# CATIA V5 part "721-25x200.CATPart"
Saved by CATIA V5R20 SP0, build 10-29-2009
Part number: 721-25x200
Definition: NONE
Nomenclature: 721-25x200
Source: Unknown
Description: 721-25x200
Bounding box of the stored display mesh (mm): x -90 to 110, y -24 to 24, z -24 to 24
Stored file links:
  C:\Users\Utente\Desktop\IO LAVORO\3D X SITO CF\X SITO\721\721-25x200.CATPart
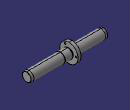
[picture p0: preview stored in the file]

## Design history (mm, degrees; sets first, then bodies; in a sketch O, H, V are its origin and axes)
Body1 "721-25x200" (main body)
  Solid1: solid without history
